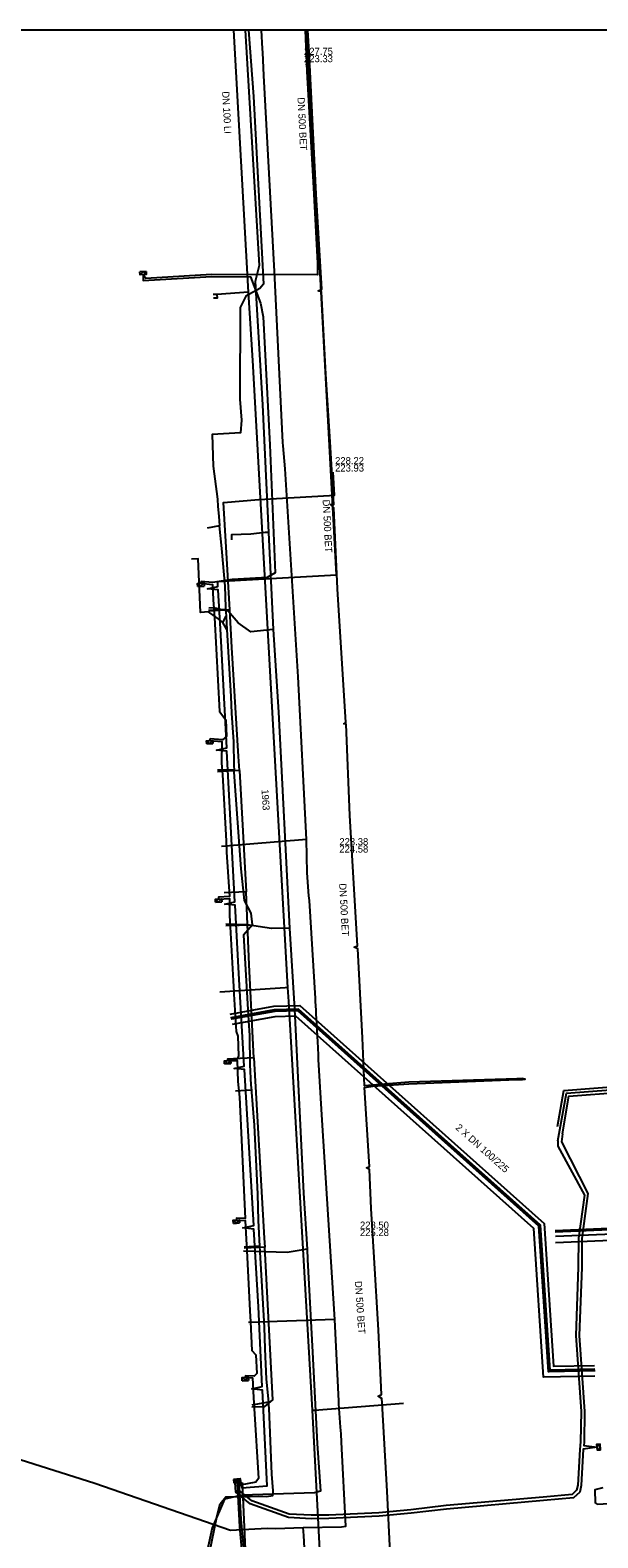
# Model space of a CAD drawing. Extents: x -599951 to -598963, y -1164095 to -1162939.
# Drawn here: x -599456.3 to -599392.1, y -1163110 to -1162939.4 of the extents above; entities that cross this region are included whole.
import ezdxf

# ---------------------------------------------------------------- set-up
doc = ezdxf.new("R2010")
doc.units = 0
for name, color, linetype in [('28', 7, 'Continuous'), ('31', 7, 'Continuous'), ('Vrstva 12', 7, 'Continuous'), ('Vrstva 13', 7, 'Continuous'), ('Vrstva 15', 7, 'Continuous'), ('Vrstva 19', 7, 'Continuous'), ('Vrstva 25', 7, 'Continuous'), ('Vrstva 37', 7, 'Continuous'), ('Vrstva 38', 7, 'Continuous'), ('Vrstva 41', 7, 'Continuous'), ('Vrstva 42', 7, 'Continuous'), ('Vrstva 43', 7, 'Continuous'), ('Vrstva 53', 7, 'Continuous'), ('Vrstva 55', 7, 'Continuous')]:
    doc.layers.add(name, color=color, linetype=linetype)

# ---------------------------------------------------------------- blocks, each defined once
blk = doc.blocks.new('NN630')
at = {"layer": '31'}
for points in [[(-0.003, -0.7), (-0.703, 0)], [(-0.703, -0.7), (-0.703, 0), (0.697, 0), (0.697, -0.7)], [(-0.003, -0.7), (0.697, 0)], [(-0.703, -0.7), (0.697, -0.7)]]:
    blk.add_lwpolyline(points, dxfattribs=at)
blk = doc.blocks.new('NN620')
at = {"layer": '28'}
for points in [[(0.752, 0.004), (-0.748, 0.004)], [(-0.748, 0.004), (-0.748, -0.746)], [(0.752, -0.746), (0.752, 0.004)], [(-0.748, -0.746), (0.752, -0.746)], [(0.368, -0.18), (-0.376, -0.18)], [(-0.376, -0.18), (-0.376, -0.558)], [(-0.376, -0.558), (0.368, -0.558)], [(0.321, -0.227), (-0.329, -0.227)], [(-0.329, -0.227), (-0.329, -0.51)], [(-0.329, -0.51), (0.321, -0.51)], [(0.274, -0.274), (-0.281, -0.274)], [(-0.281, -0.274), (-0.281, -0.463)], [(-0.281, -0.463), (0.274, -0.463)], [(0.227, -0.321), (-0.234, -0.321)], [(-0.234, -0.321), (-0.234, -0.416)], [(-0.234, -0.416), (0.227, -0.416)], [(-0.193, -0.369), (0.185, -0.369)], [(0.227, -0.416), (0.227, -0.321)], [(0.274, -0.463), (0.274, -0.274)], [(0.321, -0.51), (0.321, -0.227)], [(0.368, -0.558), (0.368, -0.18)]]:
    blk.add_lwpolyline(points, dxfattribs=at)

msp = doc.modelspace()

# ---------------------------------------------------------------- linework, layer by layer
at = {"layer": 'Vrstva 12'}
for p, q in [((-599435, -1162994.4), (-599434.89, -1162995.48)), ((-599434.89, -1162995.48), (-599436.29, -1162995.74)), ((-599433.75, -1163005.01), (-599434.16, -1162997.92)), ((-599434.18, -1163004.95), (-599436.14, -1163005.06)), ((-599433.75, -1163005.01), (-599436.14, -1163005.14)), ((-599432.65, -1163023.18), (-599432.75, -1163021.58)), ((-599435.15, -1163023.1), (-599433.25, -1163023.11)), ((-599432.65, -1163023.18), (-599435.13, -1163023.31)), ((-599432.65, -1163023.18), (-599431.9, -1163036.9)), ((-599431.9, -1163036.9), (-599434.39, -1163037.03)), ((-599434.19, -1163040.71), (-599431.17, -1163040.63)), ((-599431.03, -1163055.67), (-599433.32, -1163055.8)), ((-599431.03, -1163055.67), (-599429.85, -1163076.1)), ((-599431.3, -1163059.33), (-599433.11, -1163059.47)), ((-599429.85, -1163076.1), (-599429.79, -1163077.1)), ((-599430.37, -1163077), (-599432.13, -1163077.1)), ((-599429.79, -1163077.1), (-599432.12, -1163077.22)), ((-599429.37, -1163094.66), (-599431.25, -1163095)), ((-599436.43, -1163113.54), (-599435.17, -1163107.46))]:
    msp.add_line(p, q, dxfattribs=at)
for points in [[(-599431.63, -1162939.4), (-599431.06, -1162946.89), (-599429.93, -1162968.13), (-599430.36, -1162968.64), (-599431.93, -1162969.49), (-599432.56, -1162970.8), (-599432.61, -1162981.16), (-599432.42, -1162983.54), (-599432.52, -1162984.95), (-599435.72, -1162985.15), (-599435.63, -1162988.74), (-599435.14, -1162992.48), (-599435.11, -1162993.29), (-599435, -1162994.4)], [(-599434.16, -1162997.92), (-599434.47, -1162992.83), (-599430.46, -1162992.51), (-599422.47, -1162992.06), (-599421.88, -1162992.03), (-599422.03, -1162989.43)], [(-599434.18, -1163004.95), (-599434.18, -1163004.68), (-599434.25, -1163002.3), (-599434.66, -1162998.04), (-599434.89, -1162995.48)], [(-599436.133, -1163005.213), (-599437.07, -1163005.31), (-599437.33, -1162999.23), (-599438.09, -1162999.262)], [(-599434.54, -1163006.44), (-599435, -1163006.06), (-599435.99, -1163005.32), (-599436.133, -1163005.213)], [(-599434.54, -1163006.44), (-599434.16, -1163005.71)], [(-599434.07, -1163007.2), (-599434.54, -1163006.44)], [(-599434.18, -1163004.95), (-599434.18, -1163005.26), (-599434.16, -1163005.71)], [(-599434.16, -1163005.71), (-599434.07, -1163007.2)], [(-599432.75, -1163021.58), (-599433.5, -1163009.25), (-599433.75, -1163005.01)], [(-599434.07, -1163007.2), (-599433.64, -1163014.81)], [(-599433.64, -1163014.81), (-599433.53, -1163016.67), (-599433.34, -1163019.93), (-599433.28, -1163022.66), (-599433.25, -1163023.11)], [(-599431.17, -1163040.63), (-599431.32, -1163039.33), (-599432.09, -1163037.87), (-599432.45, -1163034.29), (-599433.24, -1163023.36), (-599433.25, -1163023.11)], [(-599431.03, -1163055.67), (-599431.54, -1163045.18), (-599431.9, -1163036.9)], [(-599431.17, -1163040.63), (-599432.19, -1163041.8), (-599431.62, -1163051.5)], [(-599431.62, -1163051.5), (-599431.52, -1163053.17), (-599431.47, -1163056.43), (-599431.35, -1163058.77), (-599431.3, -1163059.33)], [(-599431.3, -1163059.33), (-599431.28, -1163059.58), (-599431, -1163063.32), (-599430.62, -1163071.11), (-599430.54, -1163074.1), (-599430.37, -1163077)], [(-599431.24, -1163095.19), (-599429.77, -1163095.13), (-599428.86, -1163094.38), (-599429.79, -1163077.1)], [(-599430.37, -1163077), (-599429.85, -1163086.16), (-599429.77, -1163088.62), (-599429.63, -1163092.06), (-599429.37, -1163094.66)], [(-599391.55, -1163104.34), (-599392.43, -1163104.55), (-599392.39, -1163106.03), (-599392.17, -1163106.19), (-599386.73, -1163105.9), (-599373.68, -1163105.12), (-599373.42, -1163104.99), (-599373.72, -1163097.99), (-599373.94, -1163094.39), (-599374.14, -1163084.71)], [(-599435.17, -1163107.46), (-599434.82, -1163106.16), (-599434.2, -1163105.37), (-599433.04, -1163105.33), (-599431.43, -1163105.33), (-599430.54, -1163105.28), (-599429.6, -1163105.34), (-599428.89, -1163105.2), (-599428.83, -1163104.67), (-599429, -1163102.81), (-599429.3, -1163095.31), (-599429.37, -1163094.66)]]:
    msp.add_lwpolyline(points, dxfattribs=at)
at = {"layer": 'Vrstva 13'}
for points in [[(-599423.04, -1163122.44), (-599422.984, -1163122.121), (-599424.367, -1163095.569), (-599427.078, -1163049.315), (-599427.163, -1163047.729), (-599431.12, -1162976.78), (-599431.631, -1162969.046), (-599433.3, -1162939.4)], [(-599431.631, -1162969.046), (-599435.21, -1162969.294), (-599435.635, -1162969.328)], [(-599435.21, -1162969.294), (-599435.178, -1162969.712), (-599435.6, -1162969.744)], [(-599427.163, -1163047.729), (-599427.481, -1163047.747), (-599434.85, -1163048.248)], [(-599424.367, -1163095.569), (-599424.14, -1163095.54), (-599414.072, -1163094.751)]]:
    msp.add_lwpolyline(points, dxfattribs=at)
at = {"layer": 'Vrstva 19'}
for points in [[(-599424.06, -1163048.97), (-599424.74, -1163037.89), (-599424.784, -1163037.356), (-599425, -1163034.75), (-599425.06, -1163030.97), (-599426.02, -1163012.57), (-599427.49, -1162989.04), (-599427.707, -1162986.432), (-599427.74, -1162986.04), (-599428.69, -1162966.7), (-599429.88, -1162944.52), (-599430.017, -1162941.932), (-599430.04, -1162941.5), (-599430.143, -1162939.4)], [(-599425.06, -1163030.97), (-599434.679, -1163031.767)], [(-599423.69, -1163055.86), (-599423.71, -1163055.44), (-599423.76, -1163054.52), (-599423.79, -1163053.93), (-599423.94, -1163051.13), (-599423.95, -1163050.84), (-599423.98, -1163050.28), (-599424.03, -1163049.33), (-599424.06, -1163048.97)], [(-599428.56, -1163108.95), (-599425.45, -1163108.84), (-599421.09, -1163108.77), (-599420.6, -1163108.68), (-599421.11, -1163099.18), (-599421.14, -1163098.25), (-599421.2, -1163097.48), (-599421.4, -1163094.821), (-599421.42, -1163094.55), (-599421.86, -1163085.31), (-599423.3, -1163062.75), (-599423.69, -1163055.86)], [(-599616.59, -1163080.56), (-599602.317, -1163074.762), (-599589.155, -1163079.668), (-599575.598, -1163084.941), (-599563.248, -1163087.9), (-599551.627, -1163087.682), (-599546.819, -1163087.795), (-599527.481, -1163091.395), (-599494.862, -1163098.063), (-599471.97, -1163097.364), (-599469.678, -1163097.583), (-599467.49, -1163097.981), (-599449.028, -1163103.799), (-599433.664, -1163109.137), (-599429.505, -1163108.918), (-599428.56, -1163108.95)], [(-599421.86, -1163085.31), (-599431.622, -1163085.631)], [(-599430.845, -1163123.938), (-599428.76, -1163123.64), (-599424.84, -1163119.75), (-599425.35, -1163109.72), (-599425.45, -1163108.84)]]:
    msp.add_lwpolyline(points, dxfattribs=at)
at = {"layer": 'Vrstva 25'}
for points in [[(-599431.993, -1162939.4), (-599430.401, -1162966.037), (-599430.866, -1162967.852), (-599430.029, -1162981.8), (-599429.346, -1162996.258)], [(-599429.346, -1162996.258), (-599429.732, -1162996.248), (-599431.354, -1162996.44), (-599433.53, -1162996.493), (-599433.566, -1162997.087)], [(-599429.346, -1162996.258), (-599428.825, -1163007.224)], [(-599428.825, -1163007.224), (-599431.369, -1163007.496), (-599432.802, -1163006.47), (-599433.929, -1163005.141), (-599435.532, -1163004.772), (-599436.129, -1163004.808)], [(-599428.825, -1163007.224), (-599428.24, -1163016.575), (-599426.994, -1163041.018)], [(-599426.994, -1163041.018), (-599429.038, -1163041.038), (-599431.762, -1163040.644), (-599434.197, -1163040.546)], [(-599426.994, -1163041.018), (-599426.427, -1163050.172), (-599425.402, -1163071.007), (-599424.996, -1163077.352)], [(-599424.996, -1163077.352), (-599427.257, -1163077.716), (-599432.196, -1163077.568)], [(-599424.996, -1163077.352), (-599424.935, -1163078.5)], [(-599424.935, -1163078.5), (-599424.376, -1163088.985), (-599423.856, -1163099.34), (-599423.491, -1163104.711), (-599424.155, -1163104.925), (-599432.325, -1163105.172), (-599434.342, -1163105.635), (-599435.741, -1163108.873), (-599437.694, -1163117.895), (-599439.378, -1163119.583), (-599440.818, -1163121.628), (-599441.11, -1163131.474), (-599441.45, -1163132.502), (-599449.749, -1163130.947), (-599460.681, -1163128.688)]]:
    msp.add_lwpolyline(points, dxfattribs=at)
at = {"layer": 'Vrstva 37'}
for points in [[(-599317.187, -1163048.75), (-599336.512, -1163049.77), (-599337.062, -1163050.029), (-599337.271, -1163050.599), (-599337.045, -1163057.239), (-599355.804, -1163058.295), (-599379.07, -1163059.686), (-599379.613, -1163059.945), (-599379.821, -1163060.51), (-599379.356, -1163074.675), (-599396.927, -1163075.422)], [(-599392.454, -1163090.918), (-599397.506, -1163091.025), (-599398.596, -1163074.632), (-599425.982, -1163050.183), (-599428.708, -1163050.272), (-599433.615, -1163051.151)], [(-599433.61, -1163051.175), (-599428.706, -1163050.296), (-599425.991, -1163050.208), (-599398.62, -1163074.644), (-599397.53, -1163091.051), (-599392.453, -1163090.943)], [(-599392.453, -1163090.968), (-599397.553, -1163091.076), (-599398.645, -1163074.656), (-599426, -1163050.233), (-599428.703, -1163050.321), (-599433.606, -1163051.2)], [(-599433.602, -1163051.252), (-599428.703, -1163050.376), (-599426.023, -1163050.286), (-599398.7, -1163074.683), (-599397.605, -1163091.13), (-599392.456, -1163091.02)], [(-599392.45, -1163091.093), (-599397.67, -1163091.204), (-599398.766, -1163074.715), (-599426.046, -1163050.36), (-599428.69, -1163050.446), (-599433.584, -1163051.323)], [(-599392.408, -1163091.098), (-599397.604, -1163091.211), (-599398.697, -1163074.735), (-599425.994, -1163050.367), (-599428.65, -1163050.451), (-599433.546, -1163051.329)], [(-599355.275, -1163058.764), (-599378.943, -1163060.179), (-599379.214, -1163060.309), (-599379.318, -1163060.591), (-599378.853, -1163074.758), (-599378.959, -1163075.043), (-599379.235, -1163075.17), (-599396.906, -1163075.921)]]:
    msp.add_lwpolyline(points, dxfattribs=at)
at = {"layer": 'Vrstva 38'}
for points in [[(-599433.69, -1163050.732), (-599428.753, -1163049.848), (-599425.826, -1163049.753), (-599398.184, -1163074.431), (-599397.109, -1163090.592), (-599392.463, -1163090.493)], [(-599392.437, -1163091.693), (-599398.231, -1163091.816), (-599398.231, -1163091.816), (-599399.348, -1163074.999), (-599426.266, -1163050.967), (-599428.627, -1163051.044), (-599433.478, -1163051.914)], [(-599396.936, -1163075.222), (-599379.562, -1163074.484), (-599380.023, -1163060.478), (-599379.773, -1163059.8), (-599379.121, -1163059.488), (-599355.317, -1163058.065)], [(-599355.233, -1163059.463), (-599378.609, -1163060.86), (-599378.148, -1163074.873), (-599378.404, -1163075.557), (-599379.067, -1163075.864), (-599396.876, -1163076.621)]]:
    msp.add_lwpolyline(points, dxfattribs=at)
at = {"layer": 'Vrstva 42'}
for points in [[(-599425.216, -1162939.4), (-599425.037, -1162944.063), (-599424.285, -1162957.25), (-599423.811, -1162965.766), (-599423.831, -1162967.1), (-599435.806, -1162967.057), (-599443.249, -1162967.488), (-599443.539, -1162967.077), (-599443.543, -1162967.733), (-599435.817, -1162967.273), (-599431.413, -1162967.326), (-599430.265, -1162970.283), (-599429.959, -1162971.836), (-599429.207, -1162986.341), (-599428.607, -1163000.791), (-599429.51, -1163001.349), (-599433.487, -1163001.555), (-599435.708, -1163001.897), (-599436.999, -1163001.779), (-599437.031, -1163001.981), (-599435.695, -1163002.12), (-599435.617, -1163003.856), (-599435.48, -1163005.876)], [(-599432.605, -1163103.221), (-599432.38, -1163104.331), (-599429.519, -1163104.13), (-599430.042, -1163093.274), (-599431.24, -1163093.14), (-599430.062, -1163092.875), (-599430.496, -1163083.861), (-599431.015, -1163075.061), (-599432.248, -1163074.933), (-599431.039, -1163074.662), (-599432.08, -1163057.024), (-599433.256, -1163056.893), (-599432.103, -1163056.625), (-599432.721, -1163046.151), (-599433.134, -1163038.418), (-599434.295, -1163038.284), (-599433.155, -1163038.019), (-599434.064, -1163020.996), (-599435.264, -1163020.863), (-599434.086, -1163020.597), (-599434.804, -1163007.149), (-599435.055, -1163002.739), (-599436.28, -1163002.61), (-599435.078, -1163002.339), (-599435.109, -1163001.786), (-599432.528, -1163001.62), (-599421.662, -1163001.028), (-599423.685, -1162964.09), (-599425.011, -1162939.4)], [(-599435.48, -1163005.876), (-599434.891, -1163016.509), (-599434.196, -1163017.435), (-599434.104, -1163019.313), (-599434.549, -1163019.69), (-599435.976, -1163019.591), (-599436.02, -1163019.784), (-599434.645, -1163019.907), (-599434.68, -1163022.336), (-599434.58, -1163023.608), (-599434.158, -1163031.187), (-599434.109, -1163032.428), (-599433.783, -1163037.429), (-599435.028, -1163037.524), (-599435.025, -1163037.716), (-599433.776, -1163037.669), (-599433.776, -1163039.586), (-599433.716, -1163040.868), (-599433.342, -1163046.988), (-599433.281, -1163048.248), (-599433.275, -1163048.494), (-599433.026, -1163052.693), (-599432.838, -1163053.241), (-599432.746, -1163055.455), (-599432.876, -1163055.812), (-599433.993, -1163055.842), (-599433.999, -1163056.001), (-599432.895, -1163055.984), (-599432.814, -1163058.359), (-599432.658, -1163060.148), (-599431.998, -1163073.883), (-599432.982, -1163073.844), (-599433.009, -1163074.045), (-599431.988, -1163074.1), (-599431.877, -1163076.206), (-599431.822, -1163077.496), (-599431.471, -1163084.307), (-599431.41, -1163085.567), (-599431.242, -1163088.817), (-599430.785, -1163089.28), (-599430.677, -1163091.388), (-599430.993, -1163091.721), (-599431.982, -1163091.687), (-599432, -1163091.851), (-599431.179, -1163091.891), (-599431.042, -1163094.108), (-599430.977, -1163095.381), (-599430.491, -1163103.286), (-599430.796, -1163103.709), (-599432.583, -1163104.046), (-599432.629, -1163103.704)], [(-599317.187, -1163048.75), (-599336.512, -1163049.77), (-599337.062, -1163050.029), (-599337.271, -1163050.599), (-599337.045, -1163057.239), (-599355.804, -1163058.295), (-599379.07, -1163059.686), (-599379.613, -1163059.945), (-599379.821, -1163060.51), (-599379.356, -1163074.675), (-599396.927, -1163075.422)], [(-599392.454, -1163090.918), (-599397.506, -1163091.025), (-599398.596, -1163074.632), (-599425.982, -1163050.183), (-599428.708, -1163050.272), (-599433.615, -1163051.151)], [(-599433.61, -1163051.175), (-599428.706, -1163050.296), (-599425.991, -1163050.208), (-599398.62, -1163074.644), (-599397.53, -1163091.051), (-599392.453, -1163090.943)], [(-599392.453, -1163090.968), (-599397.553, -1163091.076), (-599398.645, -1163074.656), (-599426, -1163050.233), (-599428.703, -1163050.321), (-599433.606, -1163051.2)], [(-599433.602, -1163051.252), (-599428.703, -1163050.376), (-599426.023, -1163050.286), (-599398.7, -1163074.683), (-599397.605, -1163091.13), (-599392.456, -1163091.02)], [(-599392.408, -1163091.098), (-599397.604, -1163091.211), (-599398.697, -1163074.735), (-599425.994, -1163050.367), (-599428.65, -1163050.451), (-599433.546, -1163051.329)], [(-599396.679, -1163063.46), (-599395.958, -1163059.371), (-599382.86, -1163058.357), (-599382.738, -1163065.936), (-599383.303, -1163066.256), (-599383.715, -1163066.337)], [(-599396.613, -1163065.093), (-599395.661, -1163059.699), (-599383.204, -1163058.734), (-599383.092, -1163065.734), (-599383.426, -1163065.924), (-599383.731, -1163065.983)], [(-599396.114, -1163064.281), (-599395.363, -1163060.027), (-599383.548, -1163059.112), (-599383.445, -1163065.532), (-599383.549, -1163065.591), (-599383.733, -1163065.627)], [(-599396.114, -1163064.281), (-599396.214, -1163065.176), (-599393.24, -1163071.03), (-599393.896, -1163076.114), (-599393.911, -1163079.394), (-599394.204, -1163087.103), (-599393.601, -1163095.697), (-599393.645, -1163099.184), (-599393.691, -1163099.559), (-599392.176, -1163099.748), (-599393.745, -1163099.959), (-599393.968, -1163104.096), (-599394.133, -1163104.837), (-599394.848, -1163105.466), (-599398.232, -1163105.781), (-599409.204, -1163106.749), (-599413.212, -1163107.219), (-599416.837, -1163107.557), (-599422.544, -1163107.822), (-599424.536, -1163107.836), (-599427.114, -1163107.716), (-599431.449, -1163106.152), (-599433.069, -1163104.824), (-599433.148, -1163103.767)], [(-599396.613, -1163065.093), (-599396.614, -1163065.663), (-599393.626, -1163071.242), (-599394.296, -1163076.086), (-599394.311, -1163079.386), (-599394.604, -1163087.109), (-599394.001, -1163095.709), (-599394.045, -1163099.156), (-599394.147, -1163099.989), (-599394.366, -1163104.042), (-599394.495, -1163104.623), (-599395.014, -1163105.08), (-599398.268, -1163105.383), (-599409.244, -1163106.351), (-599413.254, -1163106.821), (-599416.865, -1163107.157), (-599422.554, -1163107.422), (-599424.528, -1163107.436), (-599427.036, -1163107.32), (-599431.249, -1163105.8), (-599432.713, -1163104.6), (-599432.82, -1163103.8)], [(-599432.92, -1163103.806), (-599432.63, -1163108.758), (-599431.977, -1163116.167)], [(-599432.72, -1163103.794), (-599432.479, -1163107.914), (-599432.124, -1163111.869)], [(-599432.336, -1163103.724), (-599431.929, -1163112.963), (-599420.967, -1163118.771), (-599422.939, -1163134.711), (-599423.898, -1163142.447)]]:
    msp.add_lwpolyline(points, dxfattribs=at)
at = {"layer": 'Vrstva 53'}
msp.add_lwpolyline([(-599951.125, -1164094.695), (-598963.215, -1164094.695), (-598963.215, -1162939.4), (-599951.125, -1162939.4)], close=True, dxfattribs=at)
at = {"layer": 'Vrstva 55'}
msp.add_lwpolyline([(-599415.47, -1163113.95), (-599415.94, -1163104.71), (-599416.51, -1163094.73), (-599416.535, -1163094.229), (-599416.94, -1163093.98), (-599416.558, -1163093.763), (-599416.92, -1163086.52), (-599417.42, -1163078.28), (-599417.76, -1163072.75), (-599417.934, -1163068.308), (-599418.29, -1163068.15), (-599417.947, -1163067.979), (-599417.97, -1163067.4), (-599418.5, -1163059.05), (-599417.57, -1163058.89), (-599413.48, -1163058.63), (-599401.22, -1163058.15), (-599400.617, -1163058.135), (-599400.34, -1163058.1), (-599400.665, -1163058.008), (-599401.25, -1163058.06), (-599413.49, -1163058.44), (-599417.6, -1163058.78), (-599418.508, -1163058.87), (-599418.74, -1163053.42), (-599419.27, -1163043.37), (-599419.66, -1163043.15), (-599419.29, -1163043.023), (-599420.15, -1163028.26), (-599420.59, -1163017.94), (-599420.84, -1163017.9), (-599420.603, -1163017.741), (-599421.56, -1163002.6), (-599421.97, -1162993.44), (-599422.33, -1162993.08), (-599421.986, -1162993.085), (-599422.38, -1162986), (-599422.88, -1162978.31), (-599423.37, -1162969.02), (-599423.75, -1162968.9), (-599423.34, -1162968.72), (-599423.97, -1162957.95), (-599424.7, -1162943.32), (-599425.11, -1162943.27), (-599424.7, -1162943.12), (-599424.906, -1162939.4)], dxfattribs=at)

# ---------------------------------------------------------------- block references
at = {"layer": 'Vrstva 43'}
for name, p, xscale, yscale, rotation in [('NN630', (-599443.539, -1162967.077), 0.5000000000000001, 0.5, -177.00000000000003), ('NN630', (-599437.031, -1163001.981), 0.5, 0.5000000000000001, 4.000000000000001), ('NN630', (-599436.02, -1163019.784), 0.5, 0.5000000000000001, 4.000000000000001), ('NN630', (-599435.025, -1163037.716), 0.5000000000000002, 0.4999999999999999, 3.0000000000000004), ('NN630', (-599433.999, -1163056.001), 0.5, 0.5000000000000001, 4.000000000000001), ('NN630', (-599433.009, -1163074.045), 0.5, 0.5000000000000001, 4.000000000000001), ('NN630', (-599432, -1163091.851), 0.5000000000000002, 0.4999999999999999, 3.0000000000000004), ('NN630', (-599392.176, -1163099.748), 0.5, 0.5000000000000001, 94), ('NN620', (-599432.924, -1163103.733), 0.5, 0.5000000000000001, -176.00000000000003)]:
    msp.add_blockref(name, p, dxfattribs=dict(at, xscale=xscale, yscale=yscale, rotation=rotation))

# ---------------------------------------------------------------- texts
at = {"layer": 'Vrstva 12'}
for s, p in [('227.75', (-599425.346, -1162942.193)), ('223.33', (-599425.346, -1162943.025)), ('228.22', (-599421.827, -1162988.513)), ('223.93', (-599421.827, -1162989.345)), ('228.38', (-599421.345, -1163031.628)), ('224.58', (-599421.345, -1163032.46)), ('228.50', (-599419.01, -1163075.014)), ('225.28', (-599419.01, -1163075.846))]:
    msp.add_text(s, height=0.8, dxfattribs=at).set_placement(p)
for rotation, p in [(272.8998, (-599426.085, -1162947.024)), (272.84251, (-599423.238, -1162992.537)), (273.07169, (-599421.366, -1163035.959)), (273.8327, (-599419.595, -1163080.964))]:
    msp.add_text('DN 500 BET', height=0.8, rotation=rotation, dxfattribs=at).set_placement(p)
at = {"layer": 'Vrstva 15'}
for s, p in [('DN 100 LI', (-599434.61, -1162946.341)), ('1963', (-599430.148, -1163025.329))]:
    msp.add_text(s, height=0.8, rotation=273.18628, dxfattribs=at).set_placement(p)
at = {"layer": 'Vrstva 41'}
msp.add_text('2 X DN 100/225', height=0.8, rotation=318.24221, dxfattribs=at).set_placement((-599408.266, -1163063.684))

doc.saveas('drawing.dxf')
